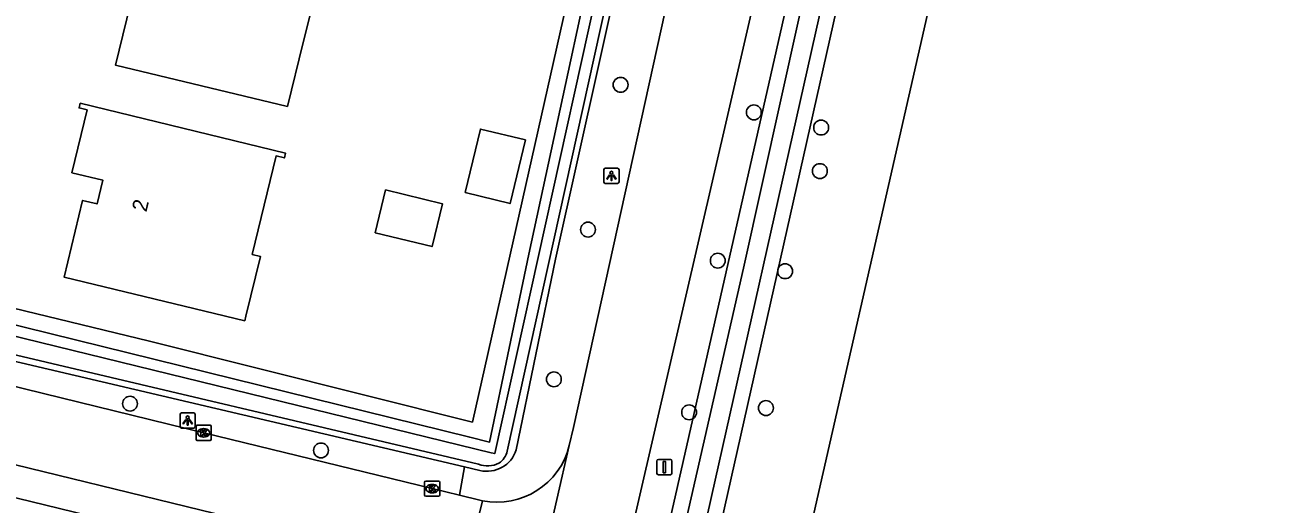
# Model space of a CAD drawing. Extents: x 163268 to 164360, y 381529 to 382285.
# Drawn here: x 164107.1 to 164189.1, y 382042.2 to 382073.8 of the extents above; entities that cross this region are included whole.
import ezdxf

# ---------------------------------------------------------------- set-up
doc = ezdxf.new("R2010")
doc.units = 0
for name, color, linetype in [('IMGEO_Boom', 7, 'Continuous'), ('IMGEO_Gemengd_bos', 7, 'Continuous'), ('IMGEO_Groenvoorziening', 7, 'Continuous'), ('IMGEO_Haag', 7, 'Continuous'), ('IMGEO_Hek', 7, 'Continuous'), ('IMGEO_Kolk', 7, 'Continuous'), ('IMGEO_Lichtpunt', 7, 'Continuous'), ('IMGEO_Pand', 7, 'Continuous'), ('IMGEO_Pand_nummerreeks', 7, 'Continuous'), ('IMGEO_Rijbaan_lokaal_gesloten', 7, 'Continuous'), ('IMGEO_Rijbaan_lokaal_open', 7, 'Continuous'), ('IMGEO_Verkeersbordpaal', 7, 'Continuous'), ('IMGEO_Voetpad_open', 7, 'Continuous'), ('IMGEO_Waterloop', 7, 'Continuous')]:
    doc.layers.add(name, color=color, linetype=linetype)

msp = doc.modelspace()

# ---------------------------------------------------------------- linework, layer by layer
at = {"layer": 'IMGEO_Boom'}
for centre in [(164146.301, 382069.815), (164155.064, 382068.001), (164159.49, 382067.004), (164159.404, 382064.137), (164144.159, 382060.287), (164152.694, 382058.244), (164157.121, 382057.548), (164141.916, 382050.429), (164114.043, 382048.828), (164155.857, 382048.54), (164150.807, 382048.259), (164126.602, 382045.751)]:
    msp.add_circle(centre, 0.489, dxfattribs=at)
at = {"layer": 'IMGEO_Gemengd_bos'}
msp.add_lwpolyline([(164143.279, 381905.933), (164077.256, 381951.167), (164080.827, 381954.421), (164084.09, 381957.395), (164099.139, 381970.079), (164134.223, 382000), (164147.955, 382011.662), (164151.333, 382014.806), (164152.631, 382016.227), (164153.21, 382017.427), (164159.013, 382041.61), (164169.547, 382087.975), (164189.14, 382176.35)], dxfattribs=at)
at = {"layer": 'IMGEO_Groenvoorziening'}
for points in [[(164181.156, 382171.056), (164182.023, 382170.778), (164168.927, 382112.378), (164153.139, 382041.967), (164150.336, 382029.47), (164148.036, 382019.209), (164143.882, 382015.495), (164139.534, 382011.626), (164124.599, 381998.968), (164119.39, 381994.553), (164100.232, 381978.315), (164089.655, 381969.35), (164073.901, 381955.997), (164072.57, 381954.591), (164072.021, 381955.239)], [(164145.156, 382021.848), (164145.336, 382022.555), (164145.515, 382023.339), (164176.186, 382158.841), (164179.124, 382171.708), (164181.156, 382171.056)], [(164163.251, 382163.045), (164165.212, 382162.647), (164142.027, 382058.344), (164139.437, 382045.789)], [(164136.031, 382044.673), (164105.091, 382051.926), (164104.316, 382052.251)], [(164135.699, 382042.803), (164136.031, 382044.673)], [(164137.051, 382044.434), (164136.031, 382044.673)]]:
    msp.add_lwpolyline(points, dxfattribs=at)
msp.add_arc((164137.514, 382046.396), 2.016, 256.71358, 342.47057, dxfattribs=at)
at = {"layer": 'IMGEO_Haag'}
for points in [[(164105.277, 382054.312), (164136.378, 382046.624), (164137.69, 382046.3), (164140.278, 382058.679), (164152.15, 382113.717), (164163.251, 382163.045)], [(164158.4, 382147.143), (164158.546, 382145.474), (164136.554, 382047.613), (164115.328, 382052.943), (164101.851, 382056.216)]]:
    msp.add_lwpolyline(points, dxfattribs=at)
at = {"layer": 'IMGEO_Hek'}
msp.add_lwpolyline([(164143.279, 381905.933), (164077.256, 381951.167), (164080.827, 381954.421), (164084.09, 381957.395), (164099.139, 381970.079), (164134.223, 382000), (164147.955, 382011.662), (164151.333, 382014.806), (164152.631, 382016.227), (164153.21, 382017.427), (164159.013, 382041.61), (164169.547, 382087.975), (164189.14, 382176.35)], dxfattribs=at)
at = {"layer": 'IMGEO_Kolk'}
for p, q in [((164118.385, 382046.484), (164118.385, 382047.336)), ((164118.46, 382047.41), (164119.312, 382047.41)), ((164118.873, 382047.19), (164118.898, 382047.19)), ((164119.386, 382047.336), (164119.386, 382046.484)), ((164119.312, 382046.41), (164118.46, 382046.41)), ((164118.896, 382046.63), (164118.871, 382046.63)), ((164133.409, 382042.811), (164133.409, 382043.663)), ((164133.484, 382043.737), (164134.336, 382043.737)), ((164133.897, 382043.517), (164133.922, 382043.517)), ((164134.41, 382043.663), (164134.41, 382042.811)), ((164134.336, 382042.737), (164133.484, 382042.737)), ((164133.92, 382042.957), (164133.895, 382042.957))]:
    msp.add_line(p, q, dxfattribs=at)
for points in [[(164118.385, 382046.484), (164118.385, 382047.336)], [(164118.46, 382047.41), (164119.312, 382047.41)], [(164119.386, 382047.336), (164119.386, 382046.484)], [(164119.312, 382046.41), (164118.46, 382046.41)], [(164118.706, 382047.11), (164118.829, 382047.11), (164118.829, 382046.959), (164118.959, 382047.11), (164119.123, 382047.11), (164118.977, 382046.959), (164119.13, 382046.71), (164118.978, 382046.71), (164118.893, 382046.874), (164118.829, 382046.807), (164118.829, 382046.71), (164118.706, 382046.71), (164118.706, 382047.11)], [(164133.409, 382042.811), (164133.409, 382043.663)], [(164133.484, 382043.737), (164134.336, 382043.737)], [(164133.73, 382043.437), (164133.853, 382043.437), (164133.853, 382043.286), (164133.983, 382043.437), (164134.147, 382043.437), (164134.001, 382043.286), (164134.154, 382043.037), (164134.002, 382043.037), (164133.917, 382043.201), (164133.853, 382043.134), (164133.853, 382043.037), (164133.73, 382043.037), (164133.73, 382043.437)], [(164134.41, 382043.663), (164134.41, 382042.811)], [(164134.336, 382042.737), (164133.484, 382042.737)]]:
    msp.add_lwpolyline(points, dxfattribs=at)
for centre, start, end in [((164118.462, 382047.334), 91.55205, 178.44795), ((164118.462, 382047.334), 91.55205, 178.44795), ((164119.31, 382047.334), 1.55205, 88.44795), ((164119.31, 382047.334), 1.55205, 88.44795), ((164118.462, 382046.486), 181.55205, 268.44795), ((164118.462, 382046.486), 181.55205, 268.44795), ((164119.31, 382046.486), 271.55205, 358.44795), ((164119.31, 382046.486), 271.55205, 358.44795), ((164133.486, 382043.661), 91.55205, 178.44795), ((164133.486, 382043.661), 91.55205, 178.44795), ((164134.334, 382043.661), 1.55205, 88.44795), ((164134.334, 382043.661), 1.55205, 88.44795), ((164133.486, 382042.813), 181.55205, 268.44795), ((164133.486, 382042.813), 181.55205, 268.44795), ((164134.334, 382042.813), 271.55205, 358.44795), ((164134.334, 382042.813), 271.55205, 358.44795)]:
    msp.add_arc(centre, 0.0765, start, end, dxfattribs=at)
for centre, major_axis, ratio, start_param, end_param in [((164118.872, 382046.91), (-0.387, 0.002), 0.722429, 4.712389, 7.853982), ((164118.897, 382046.91), (-0.39, 0.002), 0.717154, 1.570796, 4.712389), ((164133.896, 382043.237), (-0.387, 0.002), 0.722429, 4.712389, 7.853982), ((164133.921, 382043.237), (-0.39, 0.002), 0.717154, 1.570796, 4.712389)]:
    msp.add_ellipse(centre, major_axis=major_axis, ratio=ratio, start_param=start_param, end_param=end_param, dxfattribs=at)
at = {"layer": 'IMGEO_Lichtpunt'}
for p, q in [((164145.204, 382064.228), (164145.204, 382063.421)), ((164145.204, 382064.228), (164145.204, 382063.421)), ((164146.106, 382064.323), (164145.298, 382064.323)), ((164146.106, 382064.323), (164145.298, 382064.323)), ((164146.2, 382063.421), (164146.2, 382064.228)), ((164146.2, 382063.421), (164146.2, 382064.228)), ((164145.298, 382063.327), (164146.106, 382063.327)), ((164145.298, 382063.327), (164146.106, 382063.327)), ((164117.333, 382048.126), (164117.333, 382047.319)), ((164117.333, 382048.126), (164117.333, 382047.319)), ((164118.235, 382048.221), (164117.427, 382048.221)), ((164118.235, 382048.221), (164117.427, 382048.221)), ((164118.329, 382047.319), (164118.329, 382048.126)), ((164118.329, 382047.319), (164118.329, 382048.126)), ((164117.427, 382047.225), (164118.235, 382047.225)), ((164117.427, 382047.225), (164118.235, 382047.225))]:
    msp.add_line(p, q, dxfattribs=at)
for points in [[(164145.578, 382063.892), (164145.617, 382063.864), (164145.429, 382063.602), (164145.391, 382063.629), (164145.578, 382063.892)], [(164145.68, 382063.844), (164145.727, 382063.844), (164145.727, 382063.522), (164145.68, 382063.522), (164145.68, 382063.844)], [(164145.79, 382063.864), (164145.828, 382063.891), (164146.015, 382063.629), (164145.976, 382063.601), (164145.79, 382063.864)], [(164117.707, 382047.79), (164117.746, 382047.762), (164117.558, 382047.5), (164117.52, 382047.527), (164117.707, 382047.79)], [(164117.809, 382047.742), (164117.856, 382047.742), (164117.856, 382047.42), (164117.809, 382047.42), (164117.809, 382047.742)], [(164117.919, 382047.762), (164117.957, 382047.789), (164118.144, 382047.527), (164118.105, 382047.499), (164117.919, 382047.762)]]:
    msp.add_lwpolyline(points, dxfattribs=at)
for centre in [(164145.703, 382064.026), (164117.832, 382047.924)]:
    msp.add_circle(centre, 0.0994, dxfattribs=at)
for centre, start, end in [((164145.298, 382064.228), 90, 180), ((164145.298, 382064.228), 90, 180), ((164146.106, 382064.228), 0, 90), ((164146.106, 382064.228), 0, 90), ((164145.298, 382063.421), 180, 270), ((164145.298, 382063.421), 180, 270), ((164146.106, 382063.421), 270, 0), ((164146.106, 382063.421), 270, 360), ((164117.427, 382048.126), 90, 180), ((164117.427, 382048.126), 90, 180), ((164118.235, 382048.126), 0, 90), ((164118.235, 382048.126), 0, 90), ((164117.427, 382047.319), 180, 270), ((164117.427, 382047.319), 180, 270), ((164118.235, 382047.319), 270, 0), ((164118.235, 382047.319), 270, 360)]:
    msp.add_arc(centre, 0.0946, start, end, dxfattribs=at)
at = {"layer": 'IMGEO_Pand'}
for points in [[(164124.398, 382068.38), (164125.437, 382072.592), (164127.042, 382079.095), (164127.575, 382078.964), (164127.651, 382079.274), (164114.151, 382082.563), (164114.082, 382082.255), (164114.606, 382082.118), (164113.609, 382077.985), (164115.65, 382077.493), (164115.266, 382075.929), (164114.314, 382076.161), (164113.088, 382071.118), (164124.398, 382068.38)], [(164121.66, 382054.587), (164122.615, 382058.525), (164122.077, 382058.655), (164123.647, 382065.14), (164124.191, 382065.008), (164124.266, 382065.319), (164110.766, 382068.608), (164110.696, 382068.299), (164111.22, 382068.163), (164110.223, 382064.03), (164112.264, 382063.537), (164111.88, 382061.974), (164110.928, 382062.205), (164109.702, 382057.163), (164121.587, 382054.286), (164121.66, 382054.587)], [(164136.072, 382062.721), (164139.032, 382062), (164140.045, 382066.184), (164137.085, 382066.905), (164136.072, 382062.721)], [(164130.171, 382060.084), (164133.905, 382059.174), (164134.586, 382061.986), (164130.852, 382062.896), (164130.171, 382060.084)]]:
    msp.add_lwpolyline(points, dxfattribs=at)
at = {"layer": 'IMGEO_Rijbaan_lokaal_gesloten'}
for points in [[(164144.535, 382029.718), (164163.296, 382110.969), (164171.818, 382149.402), (164175.019, 382162.921), (164175.285, 382164.128)], [(164167.311, 382156.884), (164143.201, 382047.269), (164142.926, 382046.066)], [(164142.926, 382046.066), (164139.676, 382031.851)], [(164137.215, 382042.44), (164136.04, 382037.582)]]:
    msp.add_lwpolyline(points, dxfattribs=at)
msp.add_arc((164138.178, 382047.234), 4.889, 258.63935, 346.1848, dxfattribs=at)
at = {"layer": 'IMGEO_Rijbaan_lokaal_open'}
for points in [[(164104.425, 382050.455), (164104.762, 382050.374), (164118.886, 382046.909), (164133.91, 382043.236), (164135.699, 382042.803)], [(164136.04, 382037.582), (164135.877, 382037.627), (164132.723, 382038.387), (164119.615, 382041.598), (164103.619, 382045.508), (164103.293, 382045.61)], [(164135.699, 382042.803), (164137.05, 382042.476), (164137.215, 382042.44)]]:
    msp.add_lwpolyline(points, dxfattribs=at)
at = {"layer": 'IMGEO_Verkeersbordpaal'}
for p, q in [((164148.684, 382044.255), (164148.684, 382045.055)), ((164148.684, 382045.055), (164148.684, 382044.255)), ((164148.784, 382045.155), (164149.574, 382045.155)), ((164149.574, 382045.155), (164148.784, 382045.155)), ((164149.674, 382045.055), (164149.674, 382044.255)), ((164149.674, 382044.255), (164149.674, 382045.055)), ((164149.574, 382044.155), (164148.784, 382044.155)), ((164148.784, 382044.155), (164149.574, 382044.155))]:
    msp.add_line(p, q, dxfattribs=at)
msp.add_lwpolyline([(164149.104, 382045.03), (164149.254, 382045.03), (164149.254, 382044.28), (164149.104, 382044.28), (164149.104, 382045.03)], dxfattribs=at)
for centre, start, end in [((164148.784, 382045.055), 90, 180), ((164148.784, 382045.055), 90, 180), ((164149.574, 382045.055), 0, 90), ((164149.574, 382045.055), 360, 90), ((164148.784, 382044.255), 180, 270), ((164148.784, 382044.255), 180, 270), ((164149.574, 382044.255), 270, 0), ((164149.574, 382044.255), 270, 0)]:
    msp.add_arc(centre, 0.1, start, end, dxfattribs=at)
at = {"layer": 'IMGEO_Voetpad_open'}
msp.add_lwpolyline([(164134.456, 382035.801), (164101.04, 382043.975)], dxfattribs=at)
at = {"layer": 'IMGEO_Waterloop'}
for points in [[(164180.847, 382170.105), (164179.856, 382170.423), (164162.876, 382096.049), (164154.383, 382057.745), (164146.308, 382022.32)], [(164144.27, 382018.897), (164082.879, 381967.006), (164071.506, 381957.392), (164072.611, 381956.089), (164073.212, 381956.724), (164139.316, 382012.753), (164147.13, 382019.741), (164180.847, 382170.105)], [(164138.844, 382045.712), (164164.52, 382162.063), (164163.84, 382162.212), (164162.248, 382155.227), (164138.031, 382045.542), (164137.784, 382045.599), (164104.918, 382053.636)], [(164104.599, 382052.484), (164136.961, 382044.839)]]:
    msp.add_lwpolyline(points, dxfattribs=at)
for centre, radius, start, end in [((164137.626, 382045.953), 1.241, 303.08706, 348.80776), ((164137.55, 382046.375), 1.645, 249.02094, 297.28674)]:
    msp.add_arc(centre, radius, start, end, dxfattribs=at)

# ---------------------------------------------------------------- texts
at = {"layer": 'IMGEO_Pand_nummerreeks'}
msp.add_text('2', height=1, rotation=76.19688, dxfattribs=at).set_placement((164115.118, 382061.404))

doc.saveas('drawing.dxf')
